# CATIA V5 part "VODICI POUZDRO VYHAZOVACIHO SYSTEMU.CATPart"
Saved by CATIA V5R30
Part number: VODICI POUZDRO VYHAZOVACIHO SYSTEMU
Bounding box of the stored display mesh (mm): x -9 to 22, y -15.5 to 15.5, z -15.5 to 15.5
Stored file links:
  C:\Users\ondra\Desktop\PŘÍLOHA P III\CATIA\VODICI POUZDRO VYHAZOVACIHO SYSTEMU.CATPart
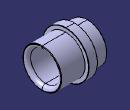
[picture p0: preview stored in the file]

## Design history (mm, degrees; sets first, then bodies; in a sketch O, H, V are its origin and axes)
Set1
  DatumSurface1 to DatumSurface24 "Z10/22x2"
  Join1: Elements (DatumSurface1; DatumSurface2; DatumSurface3; DatumSurface4; DatumSurface5; DatumSurface6; DatumSurface7; DatumSurface8; DatumSurface9; DatumSurface10; DatumSurface11; DatumSurface12; DatumSurface13; DatumSurface14; DatumSurface15; DatumSurface16; DatumSurface17; DatumSurface18; DatumSurface19; DatumSurface20; DatumSurface21; DatumSurface22; DatumSurface23; DatumSurface24)
Body1 (main body)
  CloseSurface1: CloseElement Join1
